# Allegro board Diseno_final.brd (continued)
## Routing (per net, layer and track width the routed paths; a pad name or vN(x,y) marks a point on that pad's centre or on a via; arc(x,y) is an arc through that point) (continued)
AI_1: length 78.9
  TOP w0.254: 45.81,123.91 U300.142
  TOP w0.381: R4.2 97.23,82.65 85.5,94.39 J15.1 78.36,94.39 66.45,106.3 55.68,106.3 45.81,116.16 45.81,116.18 45.8,116.19 45.8,123.9 45.81,123.91
AI_2: length 75.9
  TOP w0.254: 47.32,123.67 47.31,123.68 U300.139
  TOP w0.381: R13.2 v1(100.18,112.45) ; v1(92.18,112.45) 90.42,110.69 90.42,106.17 86.26,102.01 J15.4 73.28,102.01 67.21,108.08 56.16,108.08 47.32,116.92 47.32,123.67
  BOTTOM w0.381: v1(100.18,112.45) v1(92.18,112.45)
AI_3: length 96
  TOP w0.254: U300.138 47.81,117.31 47.83,117.29
  TOP w0.381: 47.83,117.29 47.83,117.27 56.41,108.69 67.49,108.69 71.63,104.55 J15.5 87.2,104.55 89.51,106.86 89.51,132.54 v1(91.67,134.7) ; R22.2 v1(100.05,137.97)
  BOTTOM w0.381: v1(91.67,134.7) 94.95,137.97 v1(100.05,137.97)
AI_4: length 116.8
  TOP w0.254: 49.33,123.8 49.31,123.81 U300.135
  TOP w0.381: 49.33,123.8 49.33,118.16 57.18,110.31 68.12,110.31 69.98,112.17 J15.8 85.34,112.17 86.82,113.64 86.82,161.54 v1(91.74,166.47) ; R31.2 v1(100.28,173.08)
  BOTTOM w0.381: v1(100.28,173.08) 98.35,173.08 v1(91.74,166.47)
AI_5: length 77.2
  TOP w0.254: U300.141 46.31,116.44
  TOP w0.381: R40.2 97.43,85.14 85.65,96.93 J15.2 76.68,96.93 66.67,106.93 55.78,106.93 46.31,116.4 46.31,116.44
AI_6: length 77.7
  TOP w0.254: 46.81,123.7 U300.140
  TOP w0.381: R49.2 v1(100.46,110.19) ; v1(92.18,110.19) 92.18,105.71 85.93,99.47 J15.3 74.96,99.47 66.93,107.49 55.98,107.49 46.81,116.66 46.81,123.7
  BOTTOM w0.381: v1(100.46,110.19) v1(92.18,110.19)
AI_7: length 93.8
  TOP w0.254: U300.137 48.31,123.92
  TOP w0.381: 48.31,123.92 48.3,123.92 48.3,117.7 48.31,117.7 48.31,117.63 56.67,109.27 67.72,109.27 69.9,107.09 J15.6 83.25,107.09 83.32,107.16 87.4,107.16 88.57,108.33 88.57,133.63 v1(91.52,136.58) ; R58.2 v1(100.15,140.03)
  BOTTOM w0.381: v1(100.15,140.03) 94.97,140.03 v1(91.52,136.58)
AI_8: length 115.8
  TOP w0.254: 48.81,123.71 U300.136
  TOP w0.381: R67.2 v1(100.03,168.33) ; 48.81,123.71 48.81,117.91 56.92,109.8 67.97,109.8 68.15,109.63 J15.7 86.08,109.63 87.68,111.23 87.68,158.88 v1(91.97,163.17)
  BOTTOM w0.381: v1(100.03,168.33) 97.13,168.33 v1(91.97,163.17)
AO_1: length 92.7
  TOP w0.254: 53.31,130.89 53.31,130.88 U300.114
  TOP w0.381: v1(92.28,98.73) 88.24,98.73 v1(87.43,99.54) ; v1(100.51,98.73) 113.41,98.73 114.4,97.74 U176.2 ; v1(84.23,126.19) J16.1 72.47,126.19 66.52,132.13 54.28,132.13 53.31,131.17 53.31,130.89
  BOTTOM w0.381: v1(84.23,126.19) 84.23,102.74 v1(87.43,99.54) ; v1(100.51,98.73) v1(92.28,98.73)
AO_2: length 69.8
  TOP w0.254: U300.112 52.31,131.79 52.35,131.83
  TOP w0.381: v1(101.42,126.44) 115.14,126.44 115.46,126.12 U177.2 ; 52.35,131.83 53.75,133.22 67.06,133.22 69.01,131.27 J16.3 84.16,131.27 84.19,131.24 84.76,131.24 v1(84.79,131.27) ; v1(92.56,126.44) v1(90.35,126.44)
  BOTTOM w0.381: v1(84.79,131.27) 89.61,126.44 v1(90.35,126.44) ; v1(101.42,126.44) v1(92.56,126.44)
AO_3: length 79.4
  TOP w0.254: U300.110 51.31,130.78 51.3,130.78
  TOP w0.381: v1(92.1,148.46) v1(89,145.36) ; v1(84.35,136.35) J16.5 69.44,136.35 67.44,134.34 53.37,134.34 51.31,132.29 51.31,132.27 51.3,132.26 51.3,130.78 ; v1(100.71,153.9) 112.83,153.9 113.21,154.28 U178.2
  BOTTOM w0.381: v1(89,145.36) 88.44,144.81 88.44,140.44 v1(84.35,136.35) ; v1(100.71,153.9) 97.54,153.9 v1(92.1,148.46)
AO_4: length 101.2
  TOP w0.254: U300.106 49.31,130.9 49.3,130.91
  TOP w0.381: U179.2 114.33,182.45 113.23,181.36 102.57,181.36 85.86,164.66 85.86,147.64 84.73,146.51 J16.9 76.5,146.51 66.65,136.65 52.56,136.65 49.3,133.39 49.3,130.91
AO_5: length 85.4
  TOP w0.254: U300.113 52.81,131.48 52.83,131.5
  TOP w0.381: 52.83,131.5 54.05,132.72 66.75,132.72 70.74,128.73 J16.2 v1(84.43,128.73) ; v1(92.39,103.14) 90.95,103.14 v1(88.34,100.53) ; U180.2 v1(100.29,103.14)
  BOTTOM w0.381: v1(84.43,128.73) 85.08,128.08 85.08,103.8 v1(88.34,100.53) ; v1(100.29,103.14) v1(92.39,103.14)
AO_6: length 59.9
  TOP w0.254: 51.81,130.78 U300.111
  TOP w0.381: 51.81,130.78 51.81,132.05 53.57,133.81 J16.4 84.32,133.81 84.34,133.78 v1(84.96,133.78) ; v1(92.25,130.61) v1(90.33,130.61) ; U181.2 v1(101.72,130.61)
  BOTTOM w0.381: v1(90.33,130.61) 88.13,130.61 v1(84.96,133.78) ; v1(101.72,130.61) v1(92.25,130.61)
AO_7: length 72.5
  TOP w0.254: U300.109 50.81,132.55 50.83,132.56
  TOP w0.381: 50.83,132.56 53.16,134.9 67.23,134.9 71.22,138.89 J16.6 84.12,138.89 84.13,138.89 v1(84.75,138.89) ; v1(92,150.5) v1(88.93,147.42) ; U182.2 v1(100.76,158.09)
  BOTTOM w0.381: v1(84.75,138.89) 87.78,141.93 87.78,146.28 v1(88.93,147.42) ; v1(100.76,158.09) 99.59,158.09 v1(92,150.5)
AO_8: length 92.7
  TOP w0.254: 48.79,130.99 48.81,130.97 U300.105
  TOP w0.381: 48.79,130.99 48.79,133.6 52.37,137.19 66.45,137.19 78.31,149.05 J16.10 84.28,149.05 85.24,150.01 85.24,164.92 105.89,185.57 U183.2
CLK_I: length 200.1
  TOP w0.254: U300.131 51.31,123.8
  TOP w0.381: U207.2 115.86,175.41 115.86,175.41 115.01,175.41 114.07,174.47 96.8,174.47 93.9,171.58 93.9,144.33 ; U201.2 98.41,89.4 93.9,93.9 93.9,116.87 ; 93.9,116.87 93.91,116.88 ; 93.9,116.87 93.9,144.33 ; 93.91,116.88 v1(90.31,116.88) ; 93.91,116.88 v1(94.96,116.88) ; 93.9,144.33 93.93,144.35 v1(94.89,144.35) ; U203.2 v1(105.65,116.88) ; U205.2 v1(105.33,144.35) ; v1(85.7,117.25) J15.10 73.46,117.25 67.56,111.35 57.71,111.35 51.31,117.75 51.31,123.8
  BOTTOM w0.381: v1(90.31,116.88) 86.69,116.88 86.32,117.25 v1(85.7,117.25) ; v1(105.33,144.35) v1(94.89,144.35) ; v1(105.65,116.88) v1(94.96,116.88)
CLK_I_1: length 90.9
  TOP w0.381: v1(185.24,74.04) 187.32,74.04 187.35,74.02 U34.4 ; U201.4 112.5,88.46 112.51,88.45 v1(113.13,88.45) ; U6.4 151.46,74.02 150.93,74.55 v1(150.93,75.67)
  BOTTOM w0.381: v1(113.13,88.45) 133.04,88.45 145.82,75.67 v1(150.93,75.67) 156.9,75.67 162.44,70.12 164.48,70.12 168.4,74.04 v1(185.24,74.04)
CLK_I_2: length 86
  TOP w0.381: v1(186.41,114.78) 187.03,114.78 187.19,114.63 U41.4 ; v1(151.18,115.24) 151.18,115.21 151.76,114.63 U13.4 ; U203.4 113.21,115.94 113.21,115.94 v1(113.9,115.94)
  BOTTOM w0.381: v1(113.9,115.94) 150.48,115.94 150.56,115.86 ; 150.56,115.86 157.09,115.86 163.22,109.73 165.28,109.73 170.33,114.78 v1(186.41,114.78) ; 150.56,115.86 v1(151.18,115.24)
CLK_I_3: length 91.8
  TOP w0.381: v1(112.59,143.42) 111.97,143.42 111.97,143.41 U205.4 ; U48.4 v1(184.78,155.17) ; U20.4 v1(150.14,155.17)
  BOTTOM w0.381: 149.2,156.11 149.25,156.16 157.56,156.16 162.89,150.83 165.35,150.83 169.7,155.17 v1(184.78,155.17) ; 149.2,156.11 146.28,156.11 133.56,143.39 113.24,143.39 113.22,143.42 v1(112.59,143.42) ; 149.2,156.11 v1(150.14,155.17)
CLK_I_4: length 80.6
  TOP w0.381: U27.4 151.39,196.6 151.37,196.62 v1(150.72,196.62) 128.57,174.47 U207.4 ; U55.4 v1(184,196.6)
  BOTTOM w0.381: v1(184,196.6) 151.39,196.6 151.37,196.62 v1(150.72,196.62)
CLK_O: length 187.5
  TOP w0.254: 49.81,130.93 U300.107
  TOP w0.381: v1(95.96,172.34) 98.76,169.54 98.76,159.36 ; U210.2 98.78,123.74 98.76,123.72 ; 98.76,151.21 100.86,151.21 100.88,151.22 U212.2 ; 98.76,151.21 98.76,159.36 ; 98.76,151.21 98.76,123.72 ; 49.81,130.93 49.81,130.94 49.81,133.15 52.76,136.09 66.85,136.09 74.73,143.97 J16.8 v1(84.91,143.97) ; v1(105.17,178.7) 105.82,178.7 105.82,178.7 U214.2 ; v1(91.64,157.45) v1(88.7,154.51) ; 98.76,159.36 v1(97.36,159.36) ; 98.76,123.72 98.76,96.65 99.14,96.27 U208.2
  BOTTOM w0.381: v1(97.36,159.36) 93.55,159.36 v1(91.64,157.45) ; v1(84.91,143.97) 86.64,145.69 86.64,152.45 v1(88.7,154.51) ; v1(105.17,178.7) 97.83,178.7 95.96,176.83 v1(95.96,172.34)
CLK_O_1: length 181.8
  TOP w0.381: v1(235.71,82.35) 235.2,82.85 234.44,82.85 234.01,82.42 U65.1 ; v1(268.25,82.35) 267.74,82.85 266.98,82.85 266.55,82.42 U98.1 ; v1(113.26,95.35) 112.64,95.35 112.61,95.33 U208.4
  BOTTOM w0.381: v1(268.25,82.35) v1(235.71,82.35) 208.86,82.35 198.37,71.86 196.9,71.86 193.04,75.72 167.87,75.72 164.13,71.98 162.61,71.98 156.95,77.65 146.56,77.65 128.85,95.35 v1(113.26,95.35)
CLK_O_2: length 182.6
  TOP w0.381: U210.4 112.4,122.81 112.43,122.83 v1(113.07,122.83) ; v1(235.71,114.02) 235.2,114.53 234.44,114.53 234.01,114.1 234.01,112.9 ; v1(268.25,114.02) 267.74,114.53 266.98,114.53 266.55,114.1 266.55,112.9
  BOTTOM w0.381: v1(268.25,114.02) 265.79,114.02 259.87,119.94 241.63,119.94 v1(235.71,114.02) 209.19,114.02 202.79,107.62 201.35,107.62 192.79,116.18 169.77,116.18 164.72,111.12 163.8,111.12 157.48,117.45 126.39,117.45 121.01,122.83 v1(113.07,122.83)
CLK_O_3: length 185.1
  TOP w0.381: v1(235.71,148.29) 235.2,148.79 234.44,148.79 234.01,148.36 U81.1 ; U114.1 266.55,148.36 266.98,148.79 267.74,148.79 v1(268.25,148.29) ; v1(113.03,150.29) 112.13,150.29 112.12,150.28 U212.4
  BOTTOM w0.381: v1(268.25,148.29) 263.04,148.29 257.76,153.57 245.97,153.57 240.69,148.29 v1(235.71,148.29) 226.26,148.29 218.06,156.49 208.53,156.49 202.21,150.16 199.47,150.16 192.91,156.72 169.24,156.72 164.77,152.25 163.73,152.25 158.01,157.96 145.34,157.96 137.67,150.29 v1(113.03,150.29)
CLK_O_4: length 180.5
  TOP w0.381: v1(268.25,182.32) 267.74,182.83 266.98,182.83 266.55,182.4 U122.1 ; U214.4 113.18,177.76 113.2,177.77 v1(114.22,177.77) ; U90.1 234.01,182.4 234.44,182.83 235.2,182.83 v1(235.71,182.32)
  BOTTOM w0.381: v1(268.25,182.32) 266.55,182.32 264.72,184.15 242.62,184.15 240.79,182.32 v1(235.71,182.32) 230.53,182.32 215.47,197.38 150.19,197.38 130.58,177.77 v1(114.22,177.77)
DI_01: length 63.9
  TOP w0.254: 41.81,100.94 U300.11
  TOP w0.381: 41.81,100.94 39.93,102.82 28.73,102.82 21.56,95.66 21.56,91.08 25.78,86.87 R131.2
DI_02: length 55.2
  TOP w0.254: U300.9 40.81,100.11 40.82,100.11
  TOP w0.381: 40.82,100.11 40.82,100.13 40.81,100.14 40.81,100.26 39.4,101.68 32.23,101.68 29.36,98.81 29.36,87.83 32.64,84.56 R134.2
DI_03: length 53.6
  TOP w0.254: 39.82,98.78 39.81,98.78 U300.7
  TOP w0.381: R137.2 39.6,79.38 30.63,88.34 30.63,98.32 32.74,100.43 39.07,100.43 39.81,99.69 39.81,99.39 39.82,99.38 39.82,98.78
DI_04: length 52
  TOP w0.254: U300.5 38.81,98.78 38.77,98.82 38.77,98.95
  TOP w0.381: 38.77,98.95 38.56,99.16 33.3,99.16 31.78,97.64 31.78,88.93 46.74,73.96 R141.2
DI_05: length 64.8
  TOP w0.254: U300.12 42.31,101.17
  TOP w0.381: 42.31,101.17 40.13,103.35 28.45,103.35 20.85,95.76 20.85,90.78 22.89,88.75 R120.2
DI_06: length 56.3
  TOP w0.254: 41.31,100.48 U300.10
  TOP w0.381: R123.2 29.79,86.49 28.73,87.55 28.73,99.01 32,102.29 39.7,102.29 41.31,100.67 41.31,100.48
DI_07: length 54.6
  TOP w0.254: 40.32,99.6 40.31,99.59 U300.8
  TOP w0.381: 40.32,99.6 40.32,99.9 40.31,99.9 40.31,99.92 39.17,101.07 32.51,101.07 30.02,98.58 30.02,88.06 36.65,81.43 R126.2
DI_08: length 52.9
  TOP w0.254: 39.31,98.78 U300.6
  TOP w0.381: 39.31,98.78 39.31,99.17 38.71,99.77 33.05,99.77 31.22,97.94 31.22,88.57 43.61,76.17 R129.2
DI_9: length 37.7
  TOP w0.254: U300.67 43.31,79.37
  TOP w0.381: 43.31,79.37 56.29,66.4 R156.2
DI_10: length 40.2
  TOP w0.254: U300.65 44.31,80.28
  TOP w0.381: 44.31,80.28 63.2,61.39 R159.2
DI_11: length 42.2
  TOP w0.254: 46.3,92 46.31,92.02 U300.61
  TOP w0.381: 46.3,92 46.3,90.49 46.3,90.49 46.3,90.46 70.1,66.66 R162.2
DI_12: length 44.6
  TOP w0.254: U300.59 47.31,91.8
  TOP w0.381: R165.2 76.94,61.29 47.31,90.91 47.31,91.8
DI_13: length 36.7
  TOP w0.254: U300.68 42.81,91.5 42.8,91.49
  TOP w0.381: R144.2 53.39,68.28 42.8,78.87 42.8,91.49
DI_14: length 39.2
  TOP w0.254: U300.66 43.81,79.89
  TOP w0.381: 43.81,79.89 60.3,63.4 R147.2
DI_15: length 41.2
  TOP w0.254: 45.79,91.99 45.81,92.02 U300.62
  TOP w0.381: R150.2 67.21,68.83 45.8,90.25 45.8,90.28 45.79,90.28 45.79,91.99
DI_16: length 43.6
  TOP w0.254: 46.8,92.01 46.81,92.02 U300.60
  TOP w0.381: 46.8,92.01 46.8,90.7 46.81,90.7 46.81,90.67 74.04,63.44 R153.2
DO_1: length 61.5
  TOP w0.254: U300.49 52.31,92.02 52.3,92.01 52.3,91.26
  TOP w0.381: 52.3,91.26 52.3,90.68 52.3,90.67 52.3,88.51 52.3,88.5 52.3,88.13 85.42,55.02 v1(89.48,55.02) 89.48,51.92 U146.2
  BOTTOM w0.381: v1(89.48,55.02) 90.35,55.88 R179.1
DO_2: length 66.2
  TOP w0.254: 53.31,90.25 U300.47
  TOP w0.381: 53.31,90.25 53.31,88.93 85.93,56.31 94.74,56.31 95.38,55.68 v1(95.38,55.02) 95.38,51.91 U147.2
  BOTTOM w0.381: v1(95.38,55.02) 96.14,55.78 R182.1
DO_3: length 69.3
  TOP w0.254: U300.44 54.81,92.02 54.81,92.02 54.81,90.53
  TOP w0.381: 54.81,90.53 87.66,57.68 96.67,57.68 99.36,54.99 v1(101.27,54.99) 101.27,51.9 U148.2
  BOTTOM w0.381: R185.1 101.93,56.27 101.27,55.61 v1(101.27,54.99)
DO_4: length 72.8
  TOP w0.254: 56.31,91.85 U300.41
  TOP w0.381: U149.2 v1(107.16,55.02) 105.84,56.34 99.87,56.34 97.46,58.75 89.41,58.75 56.31,91.85
  BOTTOM w0.381: v1(107.16,55.02) 107.6,55.46 107.6,55.51 107.72,55.63 R188.1
DO_5: length 72.3
  TOP w0.254: 51.81,91.49 U300.50
  TOP w0.381: 51.81,91.49 51.8,91.48 51.8,90.89 51.79,90.88 51.79,88.3 51.8,88.29 51.8,87.92 51.81,87.91 51.81,87.76 87.68,51.89 87.68,48.4 87.6,48.32 v1(87.6,47.7) 87.6,45.26 U142.2
  BOTTOM w0.381: R167.1 87.45,56.6 87.6,56.45 v1(87.6,47.7)
DO_6: length 71.5
  TOP w0.254: U300.48 52.81,91.56
  TOP w0.381: U143.2 93.47,45.28 v1(93.47,47.75) ; v1(92.13,55.47) 89.91,55.47 89.74,55.64 85.71,55.64 52.81,88.54 52.81,88.71 52.8,88.72 52.8,90.46 52.81,90.47 52.81,91.56
  BOTTOM w0.254: 93.49,54.2 93.4,54.2 v1(92.13,55.47)
  BOTTOM w0.381: R170.1 93.24,56.6 93.49,56.35 93.49,48.39 93.47,48.37 v1(93.47,47.75)
DO_7: length 75.1
  TOP w0.254: U300.45 54.31,90.26
  TOP w0.381: v1(97.64,55.45) 95.91,57.18 87.4,57.18 54.31,90.26 ; v1(99.36,47.75) 99.36,45.27 U144.2
  BOTTOM w0.381: 99.37,53.77 99.37,56.26 99.03,56.6 R173.1 ; 99.37,53.77 99.31,53.77 v1(97.64,55.45) ; 99.37,53.77 99.37,48.38 99.36,48.37 v1(99.36,47.75)
DO_8: length 78.1
  TOP w0.254: U300.42 55.81,92.02 55.8,92.01
  TOP w0.381: 55.8,92.01 55.8,91.64 89.2,58.24 97.08,58.24 99.52,55.8 103.17,55.8 v1(103.71,55.27) ; U145.2 105.26,45.26 v1(105.26,47.7)
  BOTTOM w0.381: 104.83,54.15 104.83,48.76 105.26,48.32 v1(105.26,47.7) ; 104.83,54.15 R176.1 ; 104.83,54.15 v1(103.71,55.27)
DO_09: length 97.5
  TOP w0.254: U300.40 56.31,98.78 56.32,98.78
  TOP w0.381: 56.32,98.78 56.32,98.89 58.93,101.5 64.16,101.5 114.47,51.19 v1(114.47,47.41) U150.2
  BOTTOM w0.381: R191.1 114.27,57.11 114.47,56.91 v1(114.47,47.41)
DO_10: length 100.5
  TOP w0.254: 55.31,99.51 U300.38
  TOP w0.381: v1(120.32,47.53) 120.32,46.82 120.35,46.79 U151.2 ; 55.31,99.51 58.6,102.79 64.57,102.79 111.2,56.16 v1(119.13,56.16)
  BOTTOM w0.381: v1(120.32,47.53) 120.32,48.15 120.31,48.16 120.31,55.02 ; R194.1 120.07,57.11 120.31,56.86 120.31,55.02 ; 120.31,55.02 120.27,55.02 v1(119.13,56.16)
DO_11: length 109
  TOP w0.254: U300.36 54.31,98.78 54.31,98.78 54.31,98.92
  TOP w0.381: v1(126.19,47.47) 126.19,46.85 126.24,46.8 U152.2 ; 54.31,98.92 54.32,98.94 54.32,99.67 54.3,99.69 54.3,100.11 54.32,100.12 54.32,100.32 57.99,103.99 65.28,103.99 111.71,57.56 123.06,57.56 v1(124.82,55.8)
  BOTTOM w0.381: 126.2,54.86 126.2,48.1 126.19,48.09 v1(126.19,47.47) ; 126.2,54.86 125.76,54.86 v1(124.82,55.8) ; 126.2,54.86 126.2,56.77 125.86,57.11 R197.1
DO_12: length 117.1
  TOP w0.254: U300.32 52.31,99.23 52.32,99.24
  TOP w0.381: v1(132.13,47.04) 132.13,46.42 132.12,46.41 U153.2 ; v1(130.3,56.06) 130.07,56.29 126.11,56.29 123.57,58.83 112.19,58.83 65.81,105.21 57.53,105.21 52.32,100 52.32,99.24
  BOTTOM w0.381: v1(130.3,56.06) 131.01,55.35 131.65,55.35 ; 131.65,55.35 R200.1 ; 131.65,55.35 131.65,49.19 132.12,48.72 132.12,47.68 132.13,47.66 v1(132.13,47.04)
DO_13: length 88.7
  TOP w0.254: U300.39 55.81,98.87
  TOP w0.381: U154.2 116.31,51.92 v1(116.31,55.52) 111,55.52 64.34,102.18 58.78,102.18 55.81,99.22 55.81,98.87
  BOTTOM w0.381: R203.1 117.17,56.39 v1(116.31,55.52)
DO_14: length 96.9
  TOP w0.254: U300.37 54.81,99.9
  TOP w0.381: U155.2 122.2,51.91 v1(122.2,55.52) 120.83,56.9 111.43,56.9 64.95,103.38 58.29,103.38 54.81,99.9
  BOTTOM w0.381: v1(122.2,55.52) 122.96,56.29 R206.1
DO_15: length 105.3
  TOP w0.254: U300.35 53.81,99.15
  TOP w0.381: U156.2 128.09,51.9 v1(128.09,55.5) 126,55.5 125.07,56.43 125.01,56.43 123.19,58.24 111.94,58.24 65.57,104.61 57.77,104.61 53.81,100.65 53.81,100.33 53.8,100.32 53.8,99.48 53.81,99.46 53.81,99.15
  BOTTOM w0.381: v1(128.09,55.5) 128.09,56.12 128.75,56.78 R209.1
DO_16: length 113.8
  TOP w0.254: U300.31 51.81,99.21 51.82,99.21
  TOP w0.381: 51.82,99.21 51.82,100.3 57.25,105.74 66.17,105.74 112.52,59.39 123.8,59.39 126.36,56.82 132.69,56.82 v1(133.99,55.52) U157.2
  BOTTOM w0.381: R212.1 134.54,56.13 134.43,56.02 134.43,55.96 v1(133.99,55.52)
N151383_AI_5_8: length 12.8
  TOP w0.381: U35.3 195.28,57.91 195.25,57.89 ; 195.25,57.89 R41.1 ; 195.25,57.89 194.28,56.92 192.25,56.92 191.58,56.25 C50.2
N151383_AO_5_8: length 112.3
  TOP w0.381: 263.98,94.89 263.98,94.77 264.85,95.63 v1(264.92,95.63) ; 263.98,94.89 275.84,83.03 275.84,55.98 257.73,37.87 R106.1 257.73,36.23 ; 263.98,94.89 U107.6 ; 269.77,114.99 v1(273.71,111.05) ; 269.77,114.99 C134.1 ; 269.77,114.99 269.77,115.04 268.38,116.43 266.6,116.43 265.25,115.09 265.25,112.9
  BOTTOM w0.381: v1(264.92,95.63) 265.91,96.62 265.91,103.25 v1(273.71,111.05)
PHIDI_01: length 14.8
  TOP w0.381: J1.8 35.43,18.26 27.64,26.06 R132.1
PHIDI_02: length 13.2
  TOP w0.381: R135.1 34.21,24.49 37.97,20.73 J1.9
PHIDI_03: length 11.9
  TOP w0.381: R138.1 41.1,25.2 40.51,24.61 J1.10
PHIDI_04: length 13.6
  TOP w0.381: R140.1 47.96,24.71 43.05,19.81 J1.11
PHIDI_05: length 20.8
  TOP w0.381: J1.2 34.16,15.37 31.17,15.37 23.7,22.83 R119.1
PHIDI_06: length 17.1
  TOP w0.381: J1.3 36.68,15.39 36.68,20.09 30.84,25.93 R122.1
PHIDI_07: length 15.4
  TOP w0.381: J1.4 39.22,15.39 39.22,24.49 37.59,26.11 R125.1
PHIDI_08: length 15.8
  TOP w0.381: R128.1 44.55,25.22 41.78,22.45 41.78,15.37 J1.5
PHIDI_09: length 12
  TOP w0.381: J5.8 58.29,18.8 57.35,19.74 R155.1
PHIDI_10: length 13
  TOP w0.381: R158.1 64.26,25.17 60.83,21.74 J5.9
PHIDI_11: length 14.8
  TOP w0.381: R161.1 71.17,26.85 63.37,19.05 J5.10
PHIDI_12: length 19
  TOP w0.381: R164.1 78,26.14 70.56,18.69 66.57,18.69 65.91,18.03 J5.11
PHIDI_13: length 15.8
  TOP w0.381: J5.2 57.05,15.34 57.05,17.68 54.2,20.52 R143.1
PHIDI_14: length 15.3
  TOP w0.381: R146.1 61.11,25.07 59.56,23.52 59.56,15.37 J5.3
PHIDI_15: length 17.1
  TOP w0.381: J5.4 62.1,15.37 62.1,19.91 68.02,25.83 R149.1
PHIDI_16: length 20.3
  TOP w0.381: J5.5 64.64,15.37 64.64,18.14 66.93,20.42 69.24,20.42 74.85,26.04 R152.1
PHIDO_01: length 13.1
  TOP w0.381: R181.2 90.32,22.45 93.88,18.9 J9.8
PHIDO_02: length 11.8
  TOP w0.381: R184.2 96.11,26.87 96.42,26.57 J9.9
PHIDO_03: length 12.9
  TOP w0.381: R187.2 101.9,24.84 98.96,21.89 J9.10
PHIDO_04: length 14.2
  TOP w0.381: J9.11 101.5,20.29 107.7,26.49 R190.2
PHIDO_05: length 16.9
  TOP w0.381: R169.2 87.43,23.12 92.63,17.91 92.63,15.34 J9.2
PHIDO_06: length 15.5
  TOP w0.381: R172.2 93.22,22.3 95.15,20.37 95.15,15.37 J9.3
PHIDO_07: length 15.3
  TOP w0.381: J9.4 97.69,15.37 97.69,23.62 99.01,24.94 R175.2
PHIDO_08: length 16.6
  TOP w0.381: R178.2 104.8,25.55 100.23,20.98 100.23,15.37 J9.5
PHIDO_09: length 12.7
  TOP w0.381: J13.8 116.74,18.62 114.25,21.11 R193.2
PHIDO_10: length 12
  TOP w0.381: J13.9 119.28,23.52 120.04,24.28 R196.2
PHIDO_11: length 13.3
  TOP w0.381: R199.2 125.83,23.8 121.82,19.79 J13.10
PHIDO_12: length 14.7
  TOP w0.381: J13.11 124.36,18.95 131.62,26.21 R202.2
PHIDO_13: length 15.1
  TOP w0.381: R205.2 117.14,19.91 118.01,19.05 118.01,15.37 J13.2
PHIDO_14: length 15.7
  TOP w0.381: J13.3 120.55,15.37 120.55,20.02 122.94,22.4 R208.2
PHIDO_15: length 17
  TOP w0.381: J13.4 123.09,15.37 123.09,19.61 128.73,25.25 R211.2
PHIDO_16: length 18.4
  TOP w0.381: J13.5 125.65,15.39 125.65,18.31 134.52,27.18 R214.2
N74747: length 14.7
  TOP w0.381: U126.4 24.84,46.14 20.88,50.1 20.88,54.2 22.89,56.21 R120.1
N74829: length 30.2
  TOP w0.381: R119.2 23.7,32.05 23.72,32.07 23.72,35.26 ; 23.72,35.26 v1(22.02,35.26) ; 23.72,35.26 23.72,41.47 23.9,41.64 U126.2
  BOTTOM w0.381: U184.3 24.05,47.99 24.03,47.97 R121.1 22.56,43.96 22.04,43.44 22.04,35.89 22.02,35.88 v1(22.02,35.26) 23.66,35.26 C157.1
N79416: length 14.3
  TOP w0.381: R123.1 29.79,56.57 28.22,55 28.22,49.59 31.67,46.14 U127.4
N79462: length 33.3
  TOP w0.381: R122.2 30.84,33.2 ; 30.84,33.2 v1(29.34,33.2) ; 30.84,33.2 30.84,41.54 30.73,41.64 U127.2
  BOTTOM w0.381: C158.1 30.86,33.55 30.48,33.17 29.36,33.17 v1(29.34,33.2) 29.34,43.66 29.59,43.92 30.69,43.92 R124.1 30.73,47.77 30.95,47.99 U185.3
N79945: length 14.4
  TOP w0.381: U128.4 38.51,46.14 34.98,49.67 34.98,54.43 36.65,56.11 R126.1
N79991: length 33.5
  TOP w0.381: U128.2 37.57,41.64 37.59,41.62 37.59,33.25 ; 37.59,33.25 v1(36.02,33.25) ; 37.59,33.25 R125.2
  BOTTOM w0.381: C159.1 37.62,33.66 37.21,33.25 v1(36.02,33.25) 36.02,43.74 36.29,44.01 37.39,44.01 R127.1 37.44,47.12 37.85,47.52 37.85,47.98 37.85,47.99 U186.3
N80527: length 14.3
  TOP w0.381: R129.1 43.61,56.57 41.99,54.95 41.99,49.49 45.34,46.14 U129.4
N80573: length 34
  TOP w0.381: R128.2 44.55,33.21 44.48,33.29 ; U129.2 44.4,41.64 44.48,41.57 44.48,33.29 ; 44.48,33.29 44.47,33.3 v1(42.68,33.3)
  BOTTOM w0.381: U187.3 44.75,47.45 44.15,46.84 R130.1 42.94,43.96 42.67,43.69 42.67,34.04 42.68,34.04 v1(42.68,33.3) 44.12,33.3 44.53,33.71 C160.1
N81079: length 6.1
  TOP w0.381: U130.4 27.05,54.18 25.78,55.45 R131.1
N81125: length 41.1
  TOP w0.381: R132.2 27.64,35.15 27.56,35.23 ; 27.56,35.23 v1(25.76,35.23) ; 27.56,35.23 26.11,36.68 U130.2
  BOTTOM w0.381: C161.1 26.47,35.22 26.46,35.23 v1(25.76,35.23) 25.76,43.58 26.14,43.96 R133.1 27.38,44.82 27.41,44.85 U188.3
N81639: length 6.1
  TOP w0.381: U131.4 33.88,52.83 32.64,54.08 R134.1
N81689: length 44.6
  TOP w0.381: U131.2 32.94,34.46 34.19,33.21 ; 34.19,33.21 v1(32.46,33.21) ; 34.19,33.21 34.21,33.19 R135.2
  BOTTOM w0.381: U189.3 34.31,51.65 34.09,51.43 R136.1 32.88,43.96 32.46,43.54 32.46,33.84 32.46,33.84 v1(32.46,33.21) 32.6,33.35 33.83,33.35 34.21,33.73 C162.1
N82212: length 6.1
  TOP w0.381: R137.1 39.6,55.22 40.72,54.1 U132.4
N82258: length 44.7
  TOP w0.381: v1(39.29,33.3) 39.95,33.3 39.98,33.32 41.1,33.32 ; 41.1,33.32 R138.2 ; 41.1,33.32 39.78,34.65 U132.2
  BOTTOM w0.381: U190.3 41.21,51.65 40.79,51.24 R139.1 39.59,43.96 39.29,43.66 v1(39.29,33.3) 40.79,33.3 41.12,33.63 C163.1
N84241: length 5.9
  TOP w0.381: U133.4 47.55,55.76 46.74,56.57 R141.1
N84291: length 45.7
  TOP w0.381: 47.96,32.79 46.61,34.14 U133.2 ; 47.96,32.79 46.77,32.79 46.73,32.83 v1(46.11,32.83) ; 47.96,32.79 R140.2
  BOTTOM w0.381: C164.1 47.93,33.2 47.52,32.79 46.77,32.79 46.73,32.83 v1(46.11,32.83) 46.11,33.46 46.13,33.47 46.13,43.69 46.4,43.96 R142.1 47.5,50.6 48.11,51.21 U191.3
N85989: length 4.3
  TOP w0.381: U142.4 86.69,41.3 87.43,40.56 R168.1
N86434: length 11.3
  TOP w0.381: v1(86.21,33.71) 87.12,33.71 87.43,33.4 ; 87.43,33.4 87.5,33.32 87.5,31.36 R169.1 ; 87.43,33.4 R168.2
  BOTTOM w0.381: 87.45,33.71 D65.A ; 87.45,33.71 D66.C ; 87.45,33.71 v1(86.21,33.71)
N87118: length 4.3
  TOP w0.381: U143.4 92.57,41 93.22,40.36 R171.1
N87238: length 11.3
  TOP w0.381: 93.29,33.58 v1(92.08,33.58) ; 93.29,33.58 93.29,32.22 93.22,32.15 R172.1 93.22,31.17 ; 93.29,33.58 93.29,34.76 93.22,34.83 R171.2
  BOTTOM w0.381: 93.28,33.63 D68.C ; 93.28,33.63 D67.A ; 93.28,33.63 93.23,33.58 v1(92.08,33.58)
N87595: length 4.2
  TOP w0.381: R174.1 99.01,40.18 98.46,40.73 U144.4
N87715: length 11
  TOP w0.381: R174.2 99.01,33.81 ; 99.01,33.81 v1(97.97,33.81) ; 99.01,33.81 R175.1
  BOTTOM w0.381: 99.12,31.32 D70.C 99.12,33.81 ; 99.12,33.81 v1(97.97,33.81) ; 99.12,33.81 D69.A
N88084: length 4.2
  TOP w0.381: R177.1 104.8,40.16 104.34,40.62 U145.4
N88204: length 11.5
  TOP w0.381: 104.8,33.71 104.78,33.73 v1(103.53,33.73) ; 104.8,33.71 R178.1 104.8,31.09 ; 104.8,33.71 R177.2
  BOTTOM w0.381: D72.C 104.95,33.73 ; 104.95,33.73 v1(103.53,33.73) ; 104.95,33.73 D71.A
N88589: length 11.7
  TOP w0.381: 88.57,49.56 U146.4 88.57,48.29 90.32,46.53 R180.1
N88709: length 11.2
  TOP w0.381: R180.2 90.32,33.55 ; 90.32,33.55 v1(89.05,33.55) ; 90.32,33.55 R181.1
  BOTTOM w0.381: D74.C 90.37,33.5 ; 90.37,33.5 D73.A ; 90.37,33.5 89.73,33.5 89.67,33.55 v1(89.05,33.55)
N89108: length 11.4
  TOP w0.381: R183.1 96.11,46.53 94.44,48.21 94.44,49.28 U147.4
N89151: length 14.4
  TOP w0.381: U135.4 62.08,46.28 58.6,49.76 58.6,54.87 60.3,56.57 R147.1
N89207: length 35
  TOP w0.381: v1(59.99,33.2) 61.09,33.2 61.11,33.17 ; U135.2 61.14,41.64 61.11,41.62 61.11,33.17 ; 61.11,33.17 R146.2
  BOTTOM w0.381: 61.09,33.2 61.06,33.17 61.06,31.22 ; 61.09,33.2 v1(59.99,33.2) 59.49,33.71 59.49,43.55 59.87,43.93 R148.1 61.14,47.99 61.13,47.99 U193.3 ; 61.09,33.2 61.09,34.23 61.11,34.25 C166.1
N89228: length 11.3
  TOP w0.381: 96.11,33.73 R184.1 96.11,31.09 ; 96.11,33.73 R183.2 ; 96.11,33.73 v1(95,33.73)
  BOTTOM w0.381: 96.2,31.37 D76.C 96.2,33.73 ; 96.2,33.73 D75.A ; 96.2,33.73 v1(95,33.73)
N89405: length 14.7
  TOP w0.381: U136.4 68.99,46.14 65.13,50 65.13,54.49 67.21,56.57 R150.1
N89461: length 35
  TOP w0.381: 68.02,33.17 68,33.2 v1(66.9,33.2) ; 68.02,33.17 68.02,41.62 68.05,41.64 U136.2 ; 68.02,33.17 R149.2
  BOTTOM w0.381: C167.1 68.02,34.25 68,34.23 68,33.2 ; 68,33.2 v1(66.9,33.2) 66.4,33.71 66.4,43.55 66.78,43.93 R151.1 68.05,47.98 68.03,47.99 U194.3 ; 68,33.2 67.97,33.17 67.97,31.22
N89641: length 11.3
  TOP w0.381: U148.4 100.34,47.21 101.9,45.64 R186.1
N89659: length 14.7
  TOP w0.381: U137.4 75.82,46.14 71.96,50 71.96,54.49 74.04,56.57 R153.1
N89709: length 35
  TOP w0.381: v1(73.74,33.2) 74.83,33.2 74.85,33.17 ; 74.85,33.17 R152.2 ; 74.85,33.17 74.85,41.62 74.88,41.64 U137.2
  BOTTOM w0.381: 74.83,33.2 v1(73.74,33.2) 73.23,33.71 73.23,43.55 73.61,43.93 R154.1 74.88,47.94 74.93,47.99 U195.3 ; 74.83,33.2 74.8,33.17 74.8,31.22 ; 74.83,33.2 74.83,34.23 74.85,34.25 C168.1
N89761: length 11.2
  TOP w0.381: 101.85,33.81 v1(100.89,33.81) ; 101.85,33.81 101.9,33.76 R187.1 101.9,31.09 ; 101.85,33.81 101.9,33.86 R186.2
  BOTTOM w0.381: 102.03,31.34 D78.C 102.03,33.81 ; v1(100.89,33.81) 102.03,33.81 ; 102.03,33.81 D77.A
N89929: length 6
  TOP w0.381: U138.4 57.15,55.71 56.29,56.57 R156.1
N89969: length 45.9
  TOP w0.381: U138.2 56.21,34.29 57.35,33.15 ; 57.35,33.15 57.35,33.15 R155.2 ; 57.35,33.15 v1(56.15,33.15)
  BOTTOM w0.381: 57.29,33.15 v1(56.15,33.15) 56.15,33.77 56.14,33.78 56.14,43.66 56.41,43.93 R157.1 57.58,50.95 58.09,51.46 U196.3 ; 57.29,33.15 57.29,34.17 57.37,34.25 C169.1 ; 57.29,33.15 57.32,33.11 57.32,31.22
N90183: length 6
  TOP w0.381: R159.1 63.2,56.57 64.06,55.71 U139.4
N90186: length 11.3
  TOP w0.381: R189.1 107.72,38.65 107.72,45.75 106.22,47.24 U149.4
N90223: length 45.8
  TOP w0.381: U139.2 63.12,34.29 64.26,33.15 ; 64.26,33.15 v1(63.05,33.15) ; 64.26,33.15 R158.2
  BOTTOM w0.381: 64.19,33.15 64.23,33.11 64.23,31.22 ; 64.19,33.15 64.19,34.17 64.28,34.25 C170.1 ; 64.19,33.15 v1(63.05,33.15) 63.05,33.77 63.04,33.78 63.04,43.66 63.31,43.93 R160.1 64.49,50.9 64.99,51.4 U197.3
N90306: length 11
  TOP w0.381: 107.7,33.78 R190.1 ; 107.7,33.78 v1(106.58,33.78) ; 107.7,33.78 R189.2
  BOTTOM w0.381: 107.86,33.78 D80.C ; 107.86,33.78 v1(106.58,33.78) ; 107.86,33.78 D79.A
N90437: length 6
  TOP w0.381: U140.4 70.97,55.71 70.1,56.57 R162.1
N90483: length 45.8
  TOP w0.381: U140.2 70.03,34.29 71.17,33.15 ; 71.17,33.15 R161.2 ; 71.17,33.15 v1(69.96,33.15)
  BOTTOM w0.381: 71.1,33.15 71.1,34.17 71.19,34.25 C171.1 ; 71.1,33.15 v1(69.96,33.15) 69.96,33.77 69.95,33.78 69.95,43.66 70.22,43.93 R163.1 71.4,50.88 71.89,51.37 U198.3 ; 71.1,33.15 71.14,33.11 71.14,31.22
N90675: length 6
  TOP w0.381: U141.4 77.8,55.71 76.94,56.57 R165.1
N90725: length 45.9
  TOP w0.381: U141.2 76.86,48.3 78,47.16 78,33.15 ; 78,33.15 R164.2 ; 78,33.15 v1(76.8,33.15)
  BOTTOM w0.381: C172.1 78.02,34.25 77.94,34.17 77.94,33.15 ; U199.3 78.79,51.38 78.23,50.83 R166.1 77.06,43.93 76.79,43.66 76.79,33.78 76.8,33.77 v1(76.8,33.15) 77.94,33.15 ; 77.94,33.15 77.97,33.11 77.97,31.22
N90891: length 15
  TOP w0.381: U134.4 55.17,46.14 51,50.3 51,54.19 53.39,56.57 R144.1
N90937: length 29.8
  TOP w0.381: R143.2 54.2,32.05 54.23,32.07 54.23,35.2 ; v1(52.58,35.23) 53.25,35.23 53.28,35.2 54.23,35.2 ; 54.23,35.2 U134.2
  BOTTOM w0.381: U192.3 54.23,47.99 54.23,47.99 54.23,47.77 54.22,47.76 54.22,47.24 54.23,47.23 R145.1 52.96,43.93 52.58,43.55 v1(52.58,35.23) 52.63,35.23 52.64,35.22 C165.1
N91462: length 3.8
  TOP w0.381: R192.1 114.25,40.39 113.53,41.11 U150.4
N91582: length 12.2
  TOP w0.381: R192.2 114.25,33.91 ; 114.25,33.91 113.94,34.21 v1(113.03,34.21) ; 114.25,33.91 R193.1
  BOTTOM w0.381: 114.27,34.21 D81.A ; 114.27,34.21 D82.C ; 114.27,34.21 v1(113.03,34.21)
N91694: length 3.8
  TOP w0.381: R195.1 120.04,40.44 119.41,41.06 U151.4
N91818: length 12.2
  TOP w0.381: R196.1 120.04,34.01 120.12,34.09 ; R195.2 120.04,35.34 120.12,35.26 120.12,34.09 ; 120.12,34.09 v1(118.9,34.09)
  BOTTOM w0.381: 120.11,34.14 120.06,34.09 v1(118.9,34.09) ; 120.11,34.14 D84.C ; 120.11,34.14 D83.A
N91930: length 3.7
  TOP w0.381: U152.4 125.3,41.33 125.83,40.79 R198.1
N92054: length 11.8
  TOP w0.381: R199.1 125.83,34.32 ; 125.83,34.32 v1(124.79,34.32) ; 125.83,34.32 R198.2
  BOTTOM w0.381: D85.A 125.94,34.32 ; 125.94,34.32 D86.C ; 125.94,34.32 v1(124.79,34.32)
N92166: length 3.7
  TOP w0.381: R201.1 131.62,40.51 131.17,40.97 131.17,41.68 131.18,41.69 U153.4
N92290: length 12.3
  TOP w0.381: R202.1 131.62,34.21 ; 131.62,34.21 131.6,34.24 v1(130.35,34.24) ; 131.62,34.21 R201.2
  BOTTOM w0.381: D87.A 131.77,34.24 ; 131.77,34.24 D88.C ; 131.77,34.24 v1(130.35,34.24)
N92402: length 10.9
  TOP w0.381: U154.4 115.39,47.8 117.14,46.05 R204.1
N92526: length 12.3
  TOP w0.381: R204.2 117.14,34.06 ; 117.14,34.06 R205.1 ; 117.14,34.06 v1(115.87,34.06)
  BOTTOM w0.381: D90.C 117.19,34.01 ; 117.19,34.01 D89.A ; 117.19,34.01 116.55,34.01 116.5,34.06 v1(115.87,34.06)
N92638: length 10.9
  TOP w0.381: R207.1 122.94,46.13 121.28,47.79 U155.4
N92762: length 12
  TOP w0.381: R207.2 122.94,34.24 ; 122.94,34.24 v1(121.82,34.24) ; 122.94,34.24 R208.1
  BOTTOM w0.381: 123.02,34.24 v1(121.82,34.24) ; 123.02,34.24 D92.C ; 123.02,34.24 D91.A
N92874: length 10.8
  TOP w0.381: U156.4 127.16,47.39 128.73,45.82 R210.1
N92998: length 11.8
  TOP w0.381: R211.1 128.73,34.37 ; 128.73,34.37 R210.2 ; 128.73,34.37 128.68,34.32 v1(127.71,34.32)
  BOTTOM w0.381: D94.C 128.85,34.32 ; 128.85,34.32 v1(127.71,34.32) ; 128.85,34.32 D93.A
N93110: length 10.8
  TOP w0.381: R213.1 134.52,46.38 133.05,47.85 133.05,48.35 133.04,48.35 U157.4
N93154: length 14.7
  TOP w0.381: R79.1 232.54,91.11 233.55,90.09 233.55,87.54 232.08,86.07 ; 232.08,86.07 U65.4 ; 232.08,86.07 231.69,86.46 U66.6
N93187: length 14.8
  TOP w0.381: 232.11,74.09 233.5,72.69 234.57,72.69 237.24,75.36 C89.2 ; 232.11,74.09 232.11,75.81 232.08,75.83 U65.5 ; 232.11,74.09 U67.2
N93234: length 12.1
  TOP w0.381: 134.52,34.29 v1(133.4,34.29) ; 134.52,34.29 R213.2 ; 134.52,34.29 R214.1
  BOTTOM w0.381: D95.A 134.69,34.29 ; 134.69,34.29 D96.C ; 134.69,34.29 v1(133.4,34.29)
N93303: length 71.3
  TOP w0.381: U65.3 232.71,83.41 234.06,84.76 235.84,84.76 237.24,83.36 237.24,83.29 ; v1(232.38,63.96) 232.31,63.96 231.44,63.09 ; 231.44,63.09 231.44,60.45 224.38,53.39 R82.1 ; 231.44,63.09 U67.6 ; 237.24,83.29 C89.1 ; 237.24,83.29 237.36,83.29 v1(241.35,79.3)
  BOTTOM w0.381: v1(241.35,79.3) 240.84,78.79 240.79,78.79 233.38,71.37 233.38,64.95 v1(232.38,63.96)
N93563: length 11.6
  TOP w0.381: 224.38,31.09 225.12,31.83 v1(225.5,31.83) ; 224.38,31.09 R83.1 ; 224.38,31.09 R82.2
  BOTTOM w0.381: 224.46,31.27 224.54,31.27 225.09,31.83 v1(225.5,31.83) ; 224.46,31.27 D17.A ; 224.46,31.27 D18.C
N101155: length 32.5
  TOP w0.381: 230.5,76.63 230.5,77.9 229.62,78.79 225.54,78.79 223.52,80.81 R81.2 ; 230.5,76.63 230.5,75.9 229.86,75.25 U64.2 ; 230.5,76.63 229.9,77.24 v1(229.01,77.24)
  BOTTOM w0.381: R80.1 223.47,63.53 226.92,66.98 226.92,75.62 228.55,77.24 v1(229.01,77.24)
N101611: length 8.8
  TOP w0.381: U66.2 225.26,87.12 224.54,87.85 224.54,90.47 225.17,91.11 R79.2
N101668: length 5.1
  TOP w0.381: R81.1 223.52,85.65 224.33,86.46 U66.3
N103431: length 11.6
  TOP w0.381: v1(235.05,67.56) 235.05,66.91 235.06,66.9 C87.2 233.3,64.57 232.11,65.76 U67.7
  BOTTOM w0.381: U63.2 236.02,69.7 235.05,68.73 v1(235.05,67.56)
N104801: length 8.2
  BOTTOM w0.381: R77.1 149.91,28.28 149.57,27.94 146.58,27.94 ; R78.2 146.58,27.94 ; 146.58,27.94 147.22,27.94 147.71,27.45 U61.1
N105129: length 4.8
  BOTTOM w0.381: R78.1 U60.3
N105257: length 11.4
  BOTTOM w0.381: R76.2 151.76,41.05 150.88,41.94 147.24,41.94 146.58,41.27 U60.4
N105843: length 10
  TOP w0.381: 160.66,27.48 R5.1 ; 160.66,27.48 R9.2 ; 160.66,27.48 161.01,27.13 v1(161.87,27.13)
  BOTTOM w0.381: U160.3 v1(161.87,27.13)
N106132: length 9.1
  TOP w0.381: U7.3 159.77,35.76 160.66,34.87 R5.2
N106136: length 7.6
  TOP w0.381: U7.2 159.11,38.81 158.69,38.4 156.4,38.4 v1(155.96,38.84)
  BOTTOM w0.381: v1(155.96,38.84) 155.32,39.47 R11.2
N106151: length 13.9
  TOP w0.381: 159.77,46.25 R7.2 ; 159.77,46.25 160.27,45.75 v1(161.85,45.75) ; 159.77,46.25 U7.6
  BOTTOM w0.381: v1(161.85,45.75) 161.85,44.4 160.77,43.32 R11.1
N106282: length 13.2
  TOP w0.381: 159.77,51.64 160.2,51.21 164.08,51.21 166.85,53.98 C9.1 ; 159.77,51.64 R7.1 ; 159.77,51.64 R8.2
N106462: length 12.8
  TOP w0.381: 159.77,57.89 158.8,56.92 156.77,56.92 156.09,56.25 C10.2 ; 159.77,57.89 R8.1 ; 159.77,57.89 159.79,57.91 U8.3
N106606: length 34.8
  TOP w0.381: 159.79,69.98 157.28,69.98 v1(154.86,67.56) ; 159.79,69.98 159.79,68.02 ; 159.79,69.98 R6.2 ; 159.79,68.02 160.53,68.76 162.79,68.76 166.85,64.69 C9.2 ; 159.79,68.02 U8.6
  BOTTOM w0.381: R10.1 v1(154.86,67.56)
N106624: length 14.2
  TOP w0.381: v1(157.61,59.33) 158.64,59.33 159.13,59.83 U8.2
  BOTTOM w0.381: 154.86,56.59 R10.2 ; 154.86,56.59 R12.1 ; 154.86,56.59 v1(157.61,59.33)
N106890: length 14.3
  TOP w0.381: U8.7 159.13,66.97 158.71,67.39 156.16,67.39 155.09,66.32 C7.2 153.89,65.29 153.88,65.3 v1(152.35,65.3)
  BOTTOM w0.381: v1(152.35,65.3) 152.35,62.8 151.4,61.85 U5.2
N107081: length 15.9
  TOP w0.381: v1(155.37,48.17) C5.2 158.48,46.12 159.11,45.49 U7.7
  BOTTOM w0.381: v1(155.37,48.17) 153.48,48.17 153,48.65 153,51.8 151.86,52.94 U2.2
N108762: length 19.9
  TOP w0.381: v1(162.1,39.98) 163.05,39.98 163.06,39.99 C12.2 164.26,38.91 163.63,38.28 160.88,38.28 160.4,38.76 U7.4
  BOTTOM w0.381: U9.4 163.49,49.45 162.99,48.96 162.99,42.19 162.1,41.3 v1(162.1,39.98)
N108773: length 9.3
  TOP w0.381: U8.4 160.43,60.4 161.06,59.77 161.83,59.77 161.84,59.78 C14.2 163.04,58.99 162.24,58.18 162.24,58.17 v1(161.8,57.73)
  BOTTOM w0.381: U10.4 163.49,57.76 163.46,57.73 v1(161.8,57.73)
N109129: length 4.2
  TOP w0.381: U6.3 158.71,74.02 158.72,74.03 R6.1
N109578: length 36.2
  BOTTOM w0.381: R223.1 178.93,161.77 177.9,161.77 177.09,162.59 177.09,163.22 ; 177.09,163.22 U3.1 ; 177.09,163.22 177.67,163.8 178.56,163.8 181.25,166.5 181.25,175.67 178.1,178.82 172.39,178.82 170.41,176.83 R3.2
N109817: length 6.4
  BOTTOM w0.381: 176.78,170.33 U1.2 ; 176.78,170.33 178.37,170.33 178.38,170.34 C2.2 ; 176.78,170.33 177.09,170.03 U3.5
N111654: length 8
  BOTTOM w0.381: R2.1 172.71,163.27 172.64,163.34 R1.2 171.58,164.76 171.56,164.74 169.27,164.74 168.65,165.36 U4.1
N111746: length 3.1
  BOTTOM w0.381: R2.2 174.61,163.5 175.21,164.1 U3.3
N111794: length 7.4
  BOTTOM w0.381: R3.1 170.41,170.09 171.26,169.24 174.62,169.24 175.16,168.71 175.16,168.64 175.21,168.59 U3.4
N112163: length 46.9
  TOP w0.381: U6.5 132.51,73.08 126.01,79.58 116.03,79.58 112.5,83.1 U168.2
N119962: length 13
  TOP w0.381: R83.2 224.38,24.51 229.92,18.97 J10.4
N119975: length 12
  TOP w0.381: J10.6 232.46,20.5 229.36,23.6 229.36,26.35 229.34,26.38 R87.2
N119987: length 14
  TOP w0.381: R93.2 234.39,22.83 236.25,20.98 236.25,15.34 J10.7
N119999: length 13.7
  TOP w0.381: R97.2 239.88,19.71 238.81,18.64 238.81,15.37 J10.9
N122542: length 9
  TOP w0.381: v1(168.73,27.13) 167.64,27.13 167.26,27.51 ; 167.26,27.51 R17.2 ; 167.26,27.51 R18.1
  BOTTOM w0.381: U161.3 v1(168.73,27.13)
N122562: length 55.6
  TOP w0.381: U14.3 159.77,78.31 171.04,67.03 171.04,37.26 167.26,33.48 R18.2
N122563: length 10.9
  TOP w0.381: J14.4 252.78,26.4 252.68,26.51 R102.2
N122566: length 7.2
  TOP w0.381: v1(155.35,80.14) 156.22,79.27 158.73,79.27 159.11,79.64 U14.2
  BOTTOM w0.381: R20.2 155.32,80.78 155.35,80.76 v1(155.35,80.14)
N122567: length 11.9
  TOP w0.381: J14.6 255.32,18.47 257.73,20.88 R107.2 257.73,27.56
N122571: length 15.4
  TOP w0.381: J14.7 259.13,15.37 259.13,18.52 262.64,22.02 R112.2 262.64,27.51
N122574: length 13.9
  TOP w0.381: 159.77,86.87 U14.6 ; 159.77,86.87 160.27,86.36 v1(161.85,86.36) ; 159.77,86.87 R15.2
  BOTTOM w0.381: v1(161.85,86.36) 161.85,85.01 160.77,83.93 R20.1
N122575: length 16.1
  TOP w0.381: R117.2 268.17,26.02 268.2,26 268.2,24.43 261.7,17.93 261.7,15.39 J14.9
N122594: length 13.2
  TOP w0.381: 159.77,92.25 R15.1 ; 159.77,92.25 R16.2 ; 159.77,92.25 160.2,91.82 164.08,91.82 166.85,94.59 C19.1
N122598: length 12.8
  TOP w0.381: 159.77,98.5 159.79,98.53 U15.3 ; 159.77,98.5 158.8,97.54 156.77,97.54 156.09,96.86 C20.2 ; 159.77,98.5 R16.1
N122622: length 34.9
  TOP w0.381: 159.79,108.64 160.53,109.37 162.79,109.37 166.85,105.31 C19.2 ; 159.79,108.64 U15.6 ; 159.79,108.64 159.79,110.54 ; v1(154.86,107.67) 158.24,111.05 159.28,111.05 159.79,110.54 ; 159.79,110.54 R14.2
  BOTTOM w0.381: v1(154.86,107.67) R19.1
N122634: length 14.2
  TOP w0.381: U15.2 159.13,100.44 158.64,99.95 v1(157.61,99.95)
  BOTTOM w0.381: v1(157.61,99.95) 154.86,97.21 ; 154.86,97.21 R19.2 ; 154.86,97.21 R21.1
N122662: length 14.2
  TOP w0.381: v1(152.35,105.92) 153.88,105.92 153.89,105.91 C17.2 155.09,106.7 156.4,108 158.75,108 159.13,107.62 U15.7
  BOTTOM w0.381: U12.2 151.4,102.46 152.35,103.42 v1(152.35,105.92)
N122690: length 15.9
  TOP w0.381: v1(155.37,88.79) C16.2 158.48,86.73 159.11,86.11 U14.7
  BOTTOM w0.381: U11.2 151.86,93.56 153,92.42 153,89.27 153.48,88.79 v1(155.37,88.79)
N122954: length 19.9
  TOP w0.381: U14.4 160.4,79.38 160.88,78.89 163.63,78.89 164.26,79.53 C21.2 163.06,80.6 163.05,80.59 v1(162.1,80.59)
  BOTTOM w0.381: v1(162.1,80.59) 162.1,81.92 162.99,82.8 162.99,89.57 163.49,90.07 U16.4
N122958: length 9.2
  TOP w0.381: U15.4 160.43,101.12 161.14,100.41 161.82,100.41 161.84,100.39 C24.2 163.04,99.6 162.24,98.8 162.24,98.79 v1(161.8,98.35)
  BOTTOM w0.381: U17.4 163.49,98.37 163.46,98.35 v1(161.8,98.35)
N122962: length 4.2
  TOP w0.381: U13.3 158.71,114.63 158.72,114.64 R14.1
N122974: length 33.8
  TOP w0.381: U13.5 120.87,113.69 120.36,113.18 U169.2
N123518: length 13
  TOP w0.381: J3.4 168.17,18.9 162.74,18.9 160.66,20.98 R9.1
N123530: length 9.4
  TOP w0.381: R17.1 169.35,22.44 172.97,18.82 J3.6
N123542: length 10.2
  TOP w0.381: J3.7 176.78,15.37 176.78,17.91 173.69,21.01 R23.1
N123554: length 9.1
  TOP w0.381: J3.9 179.32,15.37 179.32,19.63 179.93,20.24 R35.1
N124156: length 7.6
  TOP w0.381: R42.1 189.59,20.35 J7.4
N124168: length 6.3
  TOP w0.381: R52.1 196.39,19.13 195.83,18.57 J7.6
N124183: length 10.5
  TOP w0.381: R59.1 203,21.73 199.64,18.38 199.64,15.37 J7.7
N124195: length 14
  TOP w0.381: R71.1 209.22,19.05 205.51,15.34 202.16,15.34 J7.9
N124258: length 14.7
  TOP w0.381: 232.08,117.74 233.55,119.21 233.55,121.77 232.54,122.78 R84.1 ; 232.08,117.74 231.69,118.14 U73.6 ; 232.08,117.74 232.08,112.9
N124270: length 14.8
  TOP w0.381: 232.11,105.77 232.11,103.25 ; 232.11,105.77 232.11,107.48 232.08,107.51 U74.5 ; 232.11,105.77 233.5,104.37 234.57,104.37 237.24,107.04 C98.2
N124298: length 111.4
  TOP w0.381: U75.6 231.44,95.17 ; 231.44,95.17 244.47,82.14 244.47,63.3 229.34,48.16 R86.1 ; 231.44,95.17 231.9,95.63 v1(232.38,95.63) ; 237.24,115.04 C98.1 ; 237.24,115.04 235.84,116.43 234.06,116.43 232.71,115.09 232.71,112.9 ; 237.24,115.04 237.24,115.04 v1(241.2,111.08)
  BOTTOM w0.381: v1(232.38,95.63) 233.38,96.62 233.38,103.25 v1(241.2,111.08)
N124346: length 11.8
  TOP w0.381: 229.34,31.27 229.92,31.85 v1(230.56,31.85) ; 229.34,31.27 R86.2 ; 229.34,31.27 R87.1
  BOTTOM w0.381: v1(230.56,31.85) 230,31.85 229.39,31.24 ; 229.39,31.24 D20.C ; 229.39,31.24 D19.A
N124548: length 32.5
  TOP w0.381: U72.2 229.86,106.92 230.5,107.57 230.5,108.31 ; v1(229.01,108.92) 229.9,108.92 230.5,108.31 ; 230.5,108.31 230.5,109.58 229.97,110.11 225.9,110.11 223.52,112.48 R88.2
  BOTTOM w0.381: v1(229.01,108.92) 228.55,108.92 226.92,107.29 226.92,98.65 223.47,95.2 R85.1
N124568: length 8.8
  TOP w0.381: R84.2 225.17,122.78 224.54,122.15 224.54,119.52 225.26,118.8 U73.2
N124584: length 5.1
  TOP w0.381: R88.1 223.52,117.32 224.33,118.14 U73.3
N124764: length 11.6
  TOP w0.381: U75.7 232.11,97.43 233.3,96.24 C97.2 235.06,98.57 235.05,98.58 v1(235.05,99.24)
  BOTTOM w0.381: U71.2 236.02,101.37 235.05,100.41 v1(235.05,99.24)
N124930: length 9
  TOP w0.381: 173.69,27.53 R27.1 ; 173.69,27.53 174.09,27.13 v1(175.16,27.13) ; 173.69,27.53 R23.2 173.69,24.24
  BOTTOM w0.381: U162.3 v1(175.16,27.13)
N124958: length 96.4
  TOP w0.381: U21.3 159.77,119.61 174.62,104.75 174.62,33.6 173.69,32.66 R27.2
N124962: length 8
  TOP w0.381: U21.2 159.11,120.14 158.34,119.38 155.99,119.38 155.32,120.05 v1(155.32,120.68)
  BOTTOM w0.381: v1(155.32,120.68) R29.2
N124970: length 13.9
  TOP w0.381: 159.77,127.41 R25.2 ; 159.77,127.41 160.27,126.9 v1(161.85,126.9) ; 159.77,127.41 U21.6
  BOTTOM w0.381: v1(161.85,126.9) 161.85,125.55 160.77,124.47 R29.1
N124990: length 13.2
  TOP w0.381: 159.77,132.79 160.2,132.36 164.08,132.36 166.85,135.13 C29.1 ; 159.77,132.79 R25.1 ; 159.77,132.79 R26.2
N124994: length 12.8
  TOP w0.381: 159.77,139.04 159.79,139.06 U22.3 ; 159.77,139.04 R26.1 ; 159.77,139.04 158.8,138.07 156.77,138.07 156.09,137.4 C30.2
N125018: length 35.1
  TOP w0.381: v1(154.86,148.64) 157.71,151.49 159.38,151.49 159.79,151.08 ; 159.79,151.08 159.79,149.17 ; 159.79,151.08 R24.2 ; 159.79,149.17 U22.6 ; 159.79,149.17 160.53,149.91 162.79,149.91 166.85,145.85 C29.2
  BOTTOM w0.381: R28.1 v1(154.86,148.64)
N125030: length 14.2
  TOP w0.381: v1(157.61,140.49) 158.64,140.49 159.13,140.98 U22.2
  BOTTOM w0.381: 154.86,137.74 R28.2 ; 154.86,137.74 v1(157.61,140.49) ; 154.86,137.74 R30.1
N125058: length 14.6
  TOP w0.381: U22.7 159.13,148.29 158.75,148.67 156.15,148.67 155.09,147.61 C27.2 153.89,146.45 153.88,146.46 v1(152.35,146.46)
  BOTTOM w0.381: U19.2 151.4,143 152.35,143.95 v1(152.35,146.46)
N125086: length 15.9
  TOP w0.381: v1(155.37,129.32) C26.2 158.48,127.27 159.11,126.64 U21.7
  BOTTOM w0.381: U18.2 151.86,134.09 153,132.96 153,129.81 153.48,129.32 v1(155.37,129.32)
N125344: length 19.9
  TOP w0.381: v1(162.1,121.13) 163.05,121.13 163.06,121.14 C31.2 164.26,120.07 163.63,119.43 160.88,119.43 160.4,119.91 U21.4
  BOTTOM w0.381: U23.4 163.49,130.61 162.99,130.11 162.99,123.34 162.1,122.45 v1(162.1,121.13)
N125348: length 9.3
  TOP w0.381: U22.4 160.43,141.48 160.98,140.93 C34.2 163.04,140.14 162.24,139.34 162.24,139.33 v1(161.8,138.89)
  BOTTOM w0.381: v1(161.8,138.89) 163.46,138.89 163.49,138.91 U24.4
N125358: length 4.2
  TOP w0.381: U20.3 158.71,155.17 158.72,155.18 R24.1
N125370: length 51.2
  TOP w0.381: U170.2 111.19,138.05 113.33,135.92 129.39,135.92 147.7,154.23 U20.5
N127346: length 10.2
  TOP w0.381: 179.93,27.53 R35.2 179.93,24.29 ; 179.93,27.53 R36.1 ; 179.93,27.53 180.34,27.13 v1(182.32,27.13)
  BOTTOM w0.381: U163.3 v1(182.32,27.13)
N127374: length 139.7
  TOP w0.381: R36.2 179.93,140.08 159.77,160.25 U29.3
N127378: length 7.9
  TOP w0.381: U29.2 159.11,161.47 158.39,160.76 156.38,160.76 v1(155.32,161.82)
  BOTTOM w0.381: v1(155.32,161.82) 155.32,162.44 155.32,162.44 R38.2
N127386: length 13.9
  TOP w0.381: 159.77,168.83 160.27,168.33 v1(161.85,168.33) ; 159.77,168.83 159.77,167 ; 159.77,168.83 R33.2
  BOTTOM w0.381: v1(161.85,168.33) 161.85,166.98 160.77,165.9 R38.1
N127406: length 13.2
  TOP w0.381: C39.1 166.85,176.56 164.08,173.79 160.2,173.79 159.77,174.22 ; R34.2 159.77,174.22 ; 159.77,174.22 R33.1
N127410: length 12.8
  TOP w0.381: U28.3 159.79,180.49 159.77,180.47 ; 159.77,180.47 158.8,179.5 156.77,179.5 156.09,178.83 C40.2 ; 159.77,180.47 R34.1
N127434: length 35.1
  TOP w0.381: 159.79,190.6 159.79,192.51 ; 159.79,190.6 U28.6 ; 159.79,190.6 160.53,191.34 162.79,191.34 166.85,187.27 C39.2 ; 159.79,192.51 159.28,193.01 157.94,193.01 v1(154.86,189.94) ; 159.79,192.51 R32.2
  BOTTOM w0.381: R37.1 v1(154.86,189.94)
N127446: length 14.2
  TOP w0.381: v1(157.61,181.91) 158.64,181.91 159.13,182.41 U28.2
  BOTTOM w0.381: v1(157.61,181.91) 154.86,179.17 ; 154.86,179.17 R39.1 ; 154.86,179.17 R37.2
N127474: length 14.8
  TOP w0.381: U28.7 159.13,189.94 158.75,190.32 156.59,190.32 155.09,188.82 C37.2 153.89,187.87 153.88,187.88 v1(152.35,187.88)
  BOTTOM w0.381: U26.2 151.4,184.43 152.35,185.38 v1(152.35,187.88)
N127502: length 15.9
  TOP w0.381: v1(155.37,170.75) C36.2 158.48,168.7 159.11,168.07 159.11,167
  BOTTOM w0.381: v1(155.37,170.75) 153.48,170.75 153,171.23 153,174.38 151.86,175.52 U25.2
N127760: length 19.2
  TOP w0.381: U29.4 160.4,161.34 160.88,160.86 163.63,160.86 164.26,161.49 C41.2 162.81,162.57 162.43,162.95 v1(162.43,165.71)
  BOTTOM w0.381: v1(162.43,165.71) 162.99,166.27 162.99,171.54 163.49,172.03 U30.4
N127764: length 9.2
  TOP w0.381: v1(161.8,180.31) 162.24,180.75 162.24,180.76 163.04,181.57 C44.2 161.19,182.36 160.43,183.12 U28.4
  BOTTOM w0.381: U31.4 163.49,180.34 163.46,180.31 v1(161.8,180.31)
N127774: length 4.2
  TOP w0.381: U27.3 158.71,196.6 158.72,196.61 R32.1
N127786: length 53.4
  TOP w0.381: U171.2 111.19,172.4 112.42,171.17 126.97,171.17 151.46,195.66 U27.5
N128052: length 14.7
  TOP w0.381: 232.08,152.01 233.55,153.48 233.55,156.03 232.54,157.05 R89.1 ; 232.08,152.01 U81.4 ; 232.08,152.01 231.69,152.4 U83.6
N128064: length 14.8
  TOP w0.381: 232.11,140.03 U82.2 ; 232.11,140.03 232.11,141.74 232.08,141.77 U81.5 ; 232.11,140.03 233.5,138.63 234.57,138.63 237.24,141.3 C107.2
N128092: length 146.4
  TOP w0.381: v1(232.38,129.9) 232.31,129.9 231.44,129.03 ; v1(241.4,145.24) 240.96,145.68 240.91,145.68 240.78,145.8 240.76,145.8 237.26,149.3 237.24,149.3 ; 237.24,149.3 C107.1 ; 237.24,149.3 235.84,150.7 234.06,150.7 232.71,149.35 U81.3 ; 231.44,129.03 U82.6 ; 231.44,129.03 247.42,113.06 247.42,62.53 234.42,49.53 R92.1
  BOTTOM w0.381: v1(241.4,145.24) 233.38,137.21 233.38,130.89 v1(232.38,129.9)
N128132: length 12.3
  TOP w0.381: 234.42,31.01 234.44,31.01 235.1,31.67 v1(235.56,31.67) ; 234.42,31.01 234.42,29.76 234.39,29.73 R93.1 ; 234.42,31.01 R92.2
  BOTTOM w0.381: 234.39,31.13 D22.C ; 234.39,31.13 D21.A ; 234.39,31.13 234.94,31.67 v1(235.56,31.67)
N128330: length 32.5
  TOP w0.381: U80.2 229.86,141.19 230.5,141.84 230.5,142.57 ; v1(229.01,143.18) 229.9,143.18 230.5,142.57 ; 230.5,142.57 230.5,143.84 229.62,144.73 225.54,144.73 223.52,146.75 R91.2
  BOTTOM w0.381: v1(229.01,143.18) 228.55,143.18 226.92,141.55 226.92,132.92 223.47,129.47 R90.1
N128350: length 8.8
  TOP w0.381: R89.2 225.17,157.05 224.54,156.41 224.54,153.78 225.26,153.06 U83.2
N128366: length 5.1
  TOP w0.381: R91.1 223.52,151.59 224.33,152.4 U83.3
N128546: length 11.6
  TOP w0.381: U82.7 232.11,131.7 233.3,130.51 C106.2 235.06,132.84 235.05,132.85 v1(235.05,133.5)
  BOTTOM w0.381: v1(235.05,133.5) 235.05,134.67 236.02,135.64 U79.2
N130444: length 14.8
  TOP w0.381: U90.5 232.08,175.81 232.11,175.78 232.11,174.07 ; 232.11,174.07 233.5,172.67 234.57,172.67 237.24,175.34 C116.2 ; 232.11,174.07 U91.2
N130448: length 14.7
  TOP w0.381: R94.1 232.54,191.08 233.55,190.07 233.55,187.52 232.08,186.04 ; U89.6 231.69,186.44 232.08,186.04 ; 232.08,186.04 U90.4
N130476: length 180.6
  TOP w0.381: U91.6 231.44,163.07 ; 231.44,163.07 250.44,144.07 250.44,62.48 239.88,51.92 R96.1 ; 231.44,163.07 232.31,163.93 v1(232.38,163.93) ; 237.24,183.21 237.24,183.34 235.84,184.73 234.06,184.73 232.71,183.39 U90.3 ; 237.24,183.21 237.39,183.21 v1(241.5,179.1) ; 237.24,183.21 C116.1
  BOTTOM w0.381: v1(241.5,179.1) 233.38,170.97 233.38,164.92 v1(232.38,163.93)
N130520: length 12.1
  TOP w0.381: R97.1 239.88,31.06 ; 239.88,31.06 239.9,31.06 240.54,31.7 v1(240.92,31.7) ; 239.88,31.06 R96.2
  BOTTOM w0.381: 239.88,31.01 240.56,31.7 v1(240.92,31.7) ; 239.88,31.01 D23.A ; 239.88,31.01 D24.C
N130722: length 32.5
  TOP w0.381: 230.5,176.61 229.9,177.22 v1(229.01,177.22) ; 230.5,176.61 230.5,175.87 229.86,175.22 U88.2 ; 230.5,176.61 230.5,177.88 229.62,178.77 225.54,178.77 223.52,180.78 R98.2
  BOTTOM w0.381: R95.1 223.47,163.5 226.92,166.95 226.92,175.59 228.55,177.22 v1(229.01,177.22)
N130734: length 8.8
  TOP w0.381: U89.2 225.26,187.1 224.54,187.82 224.54,190.45 225.17,191.08 R94.2
N130754: length 5.1
  TOP w0.381: U89.3 224.33,186.44 223.52,185.62 R98.1
N130926: length 11.6
  TOP w0.381: v1(235.05,167.54) 235.05,166.88 235.06,166.87 C115.2 233.3,164.54 232.11,165.74 U91.7
  BOTTOM w0.381: U87.2 236.02,169.67 235.05,168.71 v1(235.05,167.54)
N150307: length 14.8
  TOP w0.381: 264.64,74.09 266.04,72.69 267.11,72.69 269.77,75.36 C125.2 ; 264.64,74.09 264.64,75.81 264.62,75.83 U98.5 ; 264.64,74.09 U99.2
N150319: length 14.7
  TOP w0.381: R99.1 265.07,91.11 266.09,90.09 266.09,87.54 264.62,86.07 ; U97.6 264.22,86.46 264.62,86.07 ; 264.62,86.07 U98.4
N150363: length 72.7
  TOP w0.381: 263.98,63.09 263.98,49.96 252.68,38.66 R101.1 ; 263.98,63.09 264.85,63.96 v1(264.92,63.96) ; 263.98,63.09 U99.6 ; 269.77,83.34 269.77,83.36 268.38,84.76 266.6,84.76 265.25,83.41 U98.3 ; 269.77,83.34 v1(273.71,79.4) ; 269.77,83.34 C125.1
  BOTTOM w0.381: v1(264.92,63.96) 265.91,64.95 265.91,71.58 270.56,76.23 270.56,76.25 v1(273.71,79.4)
N150395: length 14.1
  TOP w0.381: v1(250.34,32.13) 250.96,32.13 250.97,32.14 252.14,32.14 252.68,31.6 ; R101.2 252.68,31.6 ; 252.68,31.6 R102.1
  BOTTOM w0.381: D26.C 252.76,31.6 ; 252.76,31.6 D25.A ; 252.76,31.6 252.21,32.14 250.97,32.14 250.96,32.13 v1(250.34,32.13)
N150597: length 32.5
  TOP w0.381: U96.2 262.39,75.25 263.04,75.9 263.04,76.63 ; 263.04,76.63 263.04,77.9 262.15,78.79 258.08,78.79 256.06,80.81 R103.2 ; 263.04,76.63 262.43,77.24 v1(261.54,77.24)
  BOTTOM w0.381: v1(261.54,77.24) 261.09,77.24 259.46,75.62 259.46,66.98 256.01,63.53 R100.1
N150621: length 8.8
  TOP w0.381: U97.2 257.8,87.12 257.07,87.85 257.07,90.47 257.71,91.11 R99.2
N150641: length 5.1
  TOP w0.381: R103.1 256.06,85.65 256.87,86.46 U97.3
N150813: length 11.6
  TOP w0.381: U99.7 264.64,65.76 265.84,64.57 C124.2 267.6,66.9 267.59,66.91 v1(267.59,67.56)
  BOTTOM w0.381: v1(267.59,67.56) 267.59,68.73 268.55,69.7 U95.2
